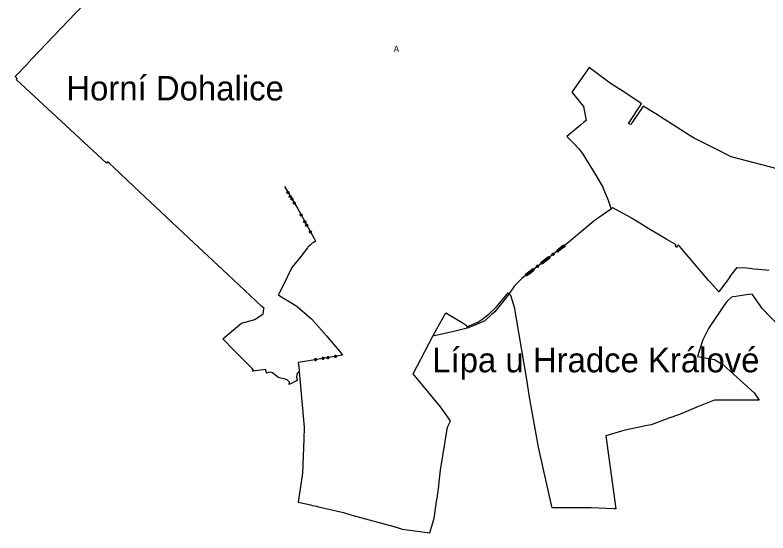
# Model space of a CAD drawing. Extents: x -648929 to -645777, y -1033280 to -1031329.
# Drawn here: x -648565 to -647340, y -1033165 to -1032322 of the extents above; entities that cross this region are included whole.
import ezdxf

# ---------------------------------------------------------------- set-up
doc = ezdxf.new("R2010")
doc.units = 0
for name, color, linetype in [('HRA_KU', 7, 'Continuous'), ('HRA_OK', 7, 'Continuous'), ('KU_RES', 7, 'Continuous'), ('OVNE_PRE', 7, 'Continuous'), ('OVNE_SET', 7, 'Continuous'), ('OVNI_SET', 7, 'Continuous'), ('POZN', 7, 'Continuous')]:
    doc.layers.add(name, color=color, linetype=linetype)

msp = doc.modelspace()

# ---------------------------------------------------------------- linework, layer by layer
at = {"layer": 'HRA_KU'}
for points in [[(-648126.7, -1032601), (-648105, -1032637.7), (-648078.9, -1032684.8), (-648076.1, -1032690.2), (-648078.2, -1032691.6), (-648081.4, -1032693.6), (-648084.7, -1032696.6), (-648088.4, -1032700), (-648089.1, -1032700.8), (-648100.1, -1032714.9), (-648114.4, -1032733), (-648121, -1032746.4), (-648122.3, -1032749), (-648136.4, -1032777.7), (-648130.7, -1032781.1), (-648116.1, -1032789.9), (-648106.3, -1032795.8), (-648085.2, -1032814.5), (-648082.8, -1032816.5), (-648058.4, -1032844.2), (-648034.5, -1032872.8), (-648032.2, -1032876), (-648087, -1032884.8), (-648104.3, -1032887.5), (-648103.6, -1032891.5), (-648103.4, -1032893.3), (-648102.6, -1032902.3)], [(-648119.2, -1032610.7), (-648119.5, -1032612), (-648120.7, -1032612.7), (-648122, -1032612.3), (-648122.6, -1032611.2), (-648122.3, -1032609.9), (-648121.2, -1032609.2), (-648119.9, -1032609.5), (-648119.2, -1032610.7), (-648119.4, -1032610.7), (-648120, -1032609.7), (-648120.5, -1032609.5), (-648119.5, -1032611.3), (-648119.6, -1032611.8), (-648121.1, -1032609.4), (-648121.4, -1032609.6), (-648120, -1032612), (-648120.3, -1032612.2), (-648121.8, -1032609.8), (-648122.1, -1032610), (-648120.7, -1032612.4), (-648121.2, -1032612.3), (-648122.2, -1032610.6), (-648122.4, -1032611.1), (-648121.8, -1032612.2)], [(-648115.3, -1032617.2), (-648115.6, -1032618.5), (-648116.8, -1032619.2), (-648118.1, -1032618.9), (-648118.7, -1032617.7), (-648118.4, -1032616.4), (-648117.3, -1032615.7), (-648116, -1032616.1), (-648115.3, -1032617.2), (-648115.5, -1032617.3), (-648116.1, -1032616.3), (-648116.6, -1032616.1), (-648115.6, -1032617.8), (-648115.7, -1032618.4), (-648117.2, -1032616), (-648117.5, -1032616.2), (-648116.1, -1032618.6), (-648116.4, -1032618.8), (-648117.9, -1032616.4), (-648118.2, -1032616.6), (-648116.8, -1032619), (-648117.3, -1032618.9), (-648118.3, -1032617.1), (-648118.5, -1032617.7), (-648117.9, -1032618.7)], [(-648112.8, -1032621.4), (-648113.1, -1032622.7), (-648114.3, -1032623.4), (-648115.6, -1032623.1), (-648116.3, -1032621.9), (-648115.9, -1032620.6), (-648114.8, -1032619.9), (-648113.5, -1032620.3), (-648112.8, -1032621.4), (-648113, -1032621.4), (-648113.6, -1032620.4), (-648114.2, -1032620.2), (-648113.2, -1032621.9), (-648113.3, -1032622.5), (-648114.7, -1032620.1), (-648115.1, -1032620.3), (-648113.7, -1032622.7), (-648114, -1032622.9), (-648115.4, -1032620.5), (-648115.8, -1032620.7), (-648114.3, -1032623.1), (-648114.9, -1032623), (-648115.9, -1032621.2), (-648116.1, -1032621.8), (-648115.4, -1032622.8)], [(-648108.9, -1032628), (-648109.2, -1032629.3), (-648110.4, -1032630), (-648111.7, -1032629.6), (-648112.4, -1032628.5), (-648112, -1032627.2), (-648110.9, -1032626.5), (-648109.6, -1032626.8), (-648108.9, -1032628), (-648109.1, -1032628), (-648109.7, -1032626.9), (-648110.3, -1032626.8), (-648109.3, -1032628.5), (-648109.4, -1032629.1), (-648110.8, -1032626.6), (-648111.2, -1032626.8), (-648109.8, -1032629.3), (-648110.1, -1032629.5), (-648111.5, -1032627.1), (-648111.9, -1032627.3), (-648110.4, -1032629.7), (-648111, -1032629.5), (-648112, -1032627.8), (-648112.2, -1032628.4), (-648111.5, -1032629.4)], [(-648097.7, -1032647.6), (-648098.1, -1032648.8), (-648099.2, -1032649.5), (-648100.5, -1032649.1), (-648101.2, -1032647.9), (-648100.8, -1032646.7), (-648099.6, -1032646), (-648098.3, -1032646.4), (-648097.7, -1032647.6), (-648097.9, -1032647.6), (-648098.5, -1032646.6), (-648099, -1032646.4), (-648098, -1032648.2), (-648098.2, -1032648.7), (-648099.6, -1032646.2), (-648099.9, -1032646.4), (-648098.6, -1032648.9), (-648098.9, -1032649.1), (-648100.3, -1032646.6), (-648100.6, -1032646.8), (-648099.3, -1032649.3), (-648099.8, -1032649.1), (-648100.8, -1032647.4), (-648100.9, -1032647.9), (-648100.3, -1032649)], [(-648091.6, -1032658.5), (-648092, -1032659.8), (-648093.2, -1032660.4), (-648094.5, -1032660.1), (-648095.1, -1032658.9), (-648094.8, -1032657.6), (-648093.6, -1032656.9), (-648092.3, -1032657.3), (-648091.6, -1032658.5), (-648091.9, -1032658.5), (-648092.5, -1032657.4), (-648093, -1032657.2), (-648092, -1032659), (-648092.2, -1032659.5), (-648093.6, -1032657.1), (-648093.9, -1032657.3), (-648092.5, -1032659.7), (-648092.9, -1032659.9), (-648094.3, -1032657.5), (-648094.6, -1032657.7), (-648093.2, -1032660.1), (-648093.8, -1032660), (-648094.8, -1032658.2), (-648094.9, -1032658.8), (-648094.3, -1032659.8)], [(-648088.6, -1032664), (-648089, -1032665.3), (-648090.1, -1032666), (-648091.4, -1032665.6), (-648092.1, -1032664.4), (-648091.7, -1032663.1), (-648090.5, -1032662.5), (-648089.2, -1032662.8), (-648088.6, -1032664), (-648088.8, -1032664.1), (-648089.4, -1032663), (-648089.9, -1032662.9), (-648088.9, -1032664.6), (-648089.1, -1032665.1), (-648090.4, -1032662.7), (-648090.8, -1032662.9), (-648089.4, -1032665.3), (-648089.8, -1032665.5), (-648091.1, -1032663.1), (-648091.5, -1032663.3), (-648090.1, -1032665.7), (-648090.7, -1032665.6), (-648091.7, -1032663.8), (-648091.8, -1032664.4), (-648091.2, -1032665.4)], [(-648082.5, -1032674.9), (-648082.9, -1032676.2), (-648084.1, -1032676.9), (-648085.4, -1032676.5), (-648086, -1032675.3), (-648085.7, -1032674), (-648084.5, -1032673.4), (-648083.2, -1032673.8), (-648082.5, -1032674.9), (-648082.8, -1032674.9), (-648083.4, -1032673.9), (-648083.9, -1032673.7), (-648082.9, -1032675.5), (-648083.1, -1032676), (-648084.4, -1032673.5), (-648084.8, -1032673.7), (-648083.4, -1032676.2), (-648083.8, -1032676.4), (-648085.1, -1032673.9), (-648085.5, -1032674.1), (-648084.1, -1032676.6), (-648084.7, -1032676.4), (-648085.6, -1032674.7), (-648085.8, -1032675.2), (-648085.2, -1032676.3)], [(-647885.1, -1032844.7), (-647878.8, -1032832.9), (-647863.9, -1032806.9), (-647837.3, -1032822.8), (-647831.1, -1032826.9), (-647830, -1032829.4), (-647812.1, -1032821.9), (-647805.7, -1032817.6), (-647793.9, -1032809), (-647781.9, -1032796.9), (-647762.6, -1032774.4), (-647760.8, -1032775.8)], [(-648076.5, -1032884.7), (-648077.6, -1032883.9), (-648077.8, -1032882.6), (-648077, -1032881.5), (-648075.7, -1032881.3), (-648074.6, -1032882.1), (-648074.4, -1032883.4), (-648075.2, -1032884.5), (-648076.5, -1032884.7), (-648076.4, -1032884.5), (-648075.2, -1032884.3), (-648074.9, -1032883.8), (-648076.8, -1032884.1), (-648077.3, -1032883.8), (-648074.5, -1032883.4), (-648074.6, -1032883), (-648077.4, -1032883.4), (-648077.4, -1032883), (-648074.7, -1032882.6), (-648074.7, -1032882.2), (-648077.5, -1032882.6), (-648077.2, -1032882.2), (-648075.2, -1032881.9), (-648075.6, -1032881.5), (-648076.8, -1032881.7)], [(-648064.2, -1032882.7), (-648065.2, -1032882), (-648065.5, -1032880.6), (-648064.7, -1032879.5), (-648063.3, -1032879.3), (-648062.2, -1032880.1), (-648062, -1032881.4), (-648062.8, -1032882.5), (-648064.2, -1032882.7), (-648064.1, -1032882.5), (-648062.9, -1032882.3), (-648062.6, -1032881.9), (-648064.6, -1032882.2), (-648065.1, -1032881.9), (-648062.3, -1032881.4), (-648062.3, -1032881), (-648065.1, -1032881.5), (-648065.2, -1032881.1), (-648062.4, -1032880.6), (-648062.5, -1032880.2), (-648065.2, -1032880.7), (-648064.9, -1032880.2), (-648062.9, -1032879.9), (-648063.4, -1032879.6), (-648064.6, -1032879.8)], [(-648056.3, -1032881.5), (-648057.4, -1032880.7), (-648057.6, -1032879.4), (-648056.8, -1032878.3), (-648055.5, -1032878.1), (-648054.4, -1032878.9), (-648054.2, -1032880.2), (-648055, -1032881.3), (-648056.3, -1032881.5), (-648056.2, -1032881.3), (-648055, -1032881.1), (-648054.7, -1032880.6), (-648056.7, -1032880.9), (-648057.1, -1032880.6), (-648054.3, -1032880.2), (-648054.4, -1032879.8), (-648057.2, -1032880.2), (-648057.2, -1032879.8), (-648054.5, -1032879.4), (-648054.5, -1032879), (-648057.3, -1032879.4), (-648057, -1032879), (-648055, -1032878.6), (-648055.5, -1032878.3), (-648056.6, -1032878.5)], [(-648044, -1032879.5), (-648045.1, -1032878.7), (-648045.3, -1032877.4), (-648044.5, -1032876.3), (-648043.1, -1032876.1), (-648042.1, -1032876.9), (-648041.8, -1032878.2), (-648042.6, -1032879.3), (-648044, -1032879.5), (-648043.9, -1032879.3), (-648042.8, -1032879.1), (-648042.4, -1032878.7), (-648044.4, -1032879), (-648044.9, -1032878.7), (-648042.1, -1032878.2), (-648042.2, -1032877.8), (-648044.9, -1032878.3), (-648045, -1032877.9), (-648042.2, -1032877.4), (-648042.3, -1032877), (-648045.1, -1032877.5), (-648044.7, -1032877), (-648042.7, -1032876.7), (-648043.2, -1032876.4), (-648044.4, -1032876.6)]]:
    msp.add_lwpolyline(points, dxfattribs=at)
at = {"layer": 'HRA_OK'}
msp.add_line((-647761.2, -1032775.5), (-647760.8, -1032775.8), dxfattribs=at)
for points in [[(-647595.3, -1032637.9), (-647599.4, -1032641), (-647614.3, -1032651.2), (-647620.5, -1032655.4), (-647626.8, -1032660.5), (-647660.2, -1032688.8), (-647664, -1032691.8), (-647740.7, -1032751.1), (-647752.6, -1032763.1), (-647758.2, -1032771.5), (-647761.2, -1032775.5)], [(-647670.2, -1032698.8), (-647675.2, -1032702.7), (-647680.3, -1032706.6), (-647682.1, -1032708), (-647684.2, -1032705.2), (-647679.2, -1032701.3), (-647674.2, -1032697.4), (-647672.3, -1032696), (-647670.2, -1032698.8), (-647670.6, -1032698.7), (-647675.6, -1032702.6), (-647680.7, -1032706.4), (-647682, -1032707.5), (-647682.3, -1032707.2), (-647677.2, -1032703.3), (-647672.2, -1032699.4), (-647670.9, -1032698.4), (-647671.1, -1032698), (-647676.1, -1032701.9), (-647681.2, -1032705.8), (-647682.5, -1032706.8), (-647682.8, -1032706.5), (-647677.7, -1032702.6), (-647672.7, -1032698.8), (-647671.4, -1032697.7), (-647671.6, -1032697.4), (-647676.6, -1032701.3), (-647681.6, -1032705.2), (-647683, -1032706.2), (-647683.2, -1032705.9), (-647678.2, -1032702), (-647673.2, -1032698.1), (-647671.8, -1032697.1), (-647672.1, -1032696.8), (-647677.1, -1032700.7), (-647682.1, -1032704.5), (-647683.5, -1032705.6), (-647683.7, -1032705.3), (-647678.7, -1032701.4), (-647673.7, -1032697.5), (-647672.3, -1032696.5)], [(-647695.5, -1032718.4), (-647700.6, -1032722.3), (-647705.6, -1032726.1), (-647707.4, -1032727.5), (-647709.6, -1032724.8), (-647704.5, -1032720.9), (-647699.5, -1032717), (-647697.7, -1032715.6), (-647695.5, -1032718.4), (-647696, -1032718.2), (-647701, -1032722.1), (-647706, -1032726), (-647707.4, -1032727), (-647707.6, -1032726.7), (-647702.6, -1032722.8), (-647697.5, -1032719), (-647696.2, -1032717.9), (-647696.4, -1032717.6), (-647701.5, -1032721.5), (-647706.5, -1032725.4), (-647707.8, -1032726.4), (-647708.1, -1032726.1), (-647703.1, -1032722.2), (-647698, -1032718.3), (-647696.7, -1032717.3), (-647696.9, -1032717), (-647702, -1032720.9), (-647707, -1032724.7), (-647708.3, -1032725.8), (-647708.6, -1032725.5), (-647703.6, -1032721.6), (-647698.5, -1032717.7), (-647697.2, -1032716.7), (-647697.4, -1032716.3), (-647702.5, -1032720.2), (-647707.5, -1032724.1), (-647708.8, -1032725.1), (-647709.1, -1032724.8), (-647704, -1032720.9), (-647699, -1032717.1), (-647697.7, -1032716)], [(-647695.1, -1032718), (-647700.2, -1032721.9), (-647705.2, -1032725.8), (-647707, -1032727.2), (-647709.2, -1032724.4), (-647704.1, -1032720.6), (-647699.1, -1032716.7), (-647697.3, -1032715.3), (-647695.1, -1032718), (-647695.6, -1032718), (-647700.7, -1032721.9), (-647705.7, -1032725.7), (-647707, -1032726.8), (-647707.3, -1032726.5), (-647702.2, -1032722.6), (-647697.2, -1032718.7), (-647695.9, -1032717.7), (-647696.1, -1032717.3), (-647701.1, -1032721.2), (-647706.2, -1032725.1), (-647707.5, -1032726.1), (-647707.8, -1032725.8), (-647702.7, -1032722), (-647697.7, -1032718.1), (-647696.4, -1032717), (-647696.6, -1032716.7), (-647701.6, -1032720.6), (-647706.7, -1032724.5), (-647708, -1032725.5), (-647708.3, -1032725.2), (-647703.2, -1032721.3), (-647698.2, -1032717.4), (-647696.9, -1032716.4), (-647697.1, -1032716.1), (-647702.1, -1032720), (-647707.2, -1032723.8), (-647708.5, -1032724.9), (-647708.7, -1032724.6), (-647703.7, -1032720.7), (-647698.7, -1032716.8), (-647697.3, -1032715.8)], [(-647688.2, -1032712.5), (-647689.3, -1032713.3), (-647690.6, -1032713.1), (-647691.4, -1032712.1), (-647691.2, -1032710.7), (-647690.2, -1032709.9), (-647688.8, -1032710.1), (-647688, -1032711.2), (-647688.2, -1032712.5), (-647688.3, -1032712.4), (-647689.3, -1032713.1), (-647689.9, -1032713), (-647688.3, -1032711.8), (-647688.2, -1032711.2), (-647690.4, -1032712.9), (-647690.7, -1032712.6), (-647688.4, -1032710.9), (-647688.7, -1032710.6), (-647690.9, -1032712.3), (-647691.2, -1032712), (-647688.9, -1032710.3), (-647689.5, -1032710.2), (-647691.1, -1032711.4), (-647691, -1032710.9), (-647690.1, -1032710.1)], [(-647720.5, -1032737.6), (-647725.5, -1032741.5), (-647730.5, -1032745.4), (-647732.4, -1032746.8), (-647734.5, -1032744), (-647729.5, -1032740.1), (-647724.4, -1032736.3), (-647722.6, -1032734.8), (-647720.5, -1032737.6), (-647721, -1032737.6), (-647726, -1032741.4), (-647731, -1032745.3), (-647732.4, -1032746.4), (-647732.6, -1032746), (-647727.6, -1032742.2), (-647722.6, -1032738.3), (-647721.2, -1032737.2), (-647721.5, -1032736.9), (-647726.5, -1032740.8), (-647731.5, -1032744.7), (-647732.9, -1032745.7), (-647733.1, -1032745.4), (-647728.1, -1032741.5), (-647723.1, -1032737.6), (-647721.7, -1032736.6), (-647721.9, -1032736.3), (-647727, -1032740.2), (-647732, -1032744), (-647733.3, -1032745.1), (-647733.6, -1032744.8), (-647728.6, -1032740.9), (-647723.5, -1032737), (-647722.2, -1032736), (-647722.4, -1032735.7), (-647727.5, -1032739.5), (-647732.5, -1032743.4), (-647733.8, -1032744.5), (-647734.1, -1032744.1), (-647729.1, -1032740.3), (-647724, -1032736.4), (-647722.7, -1032735.3)], [(-647713.5, -1032732.1), (-647714.6, -1032732.9), (-647715.9, -1032732.7), (-647716.8, -1032731.6), (-647716.6, -1032730.3), (-647715.5, -1032729.5), (-647714.2, -1032729.7), (-647713.4, -1032730.7), (-647713.5, -1032732.1), (-647713.7, -1032731.9), (-647714.6, -1032732.7), (-647715.2, -1032732.6), (-647713.6, -1032731.4), (-647713.5, -1032730.8), (-647715.8, -1032732.5), (-647716, -1032732.2), (-647713.8, -1032730.5), (-647714, -1032730.2), (-647716.3, -1032731.9), (-647716.5, -1032731.6), (-647714.3, -1032729.9), (-647714.8, -1032729.8), (-647716.4, -1032731), (-647716.4, -1032730.5), (-647715.4, -1032729.7)]]:
    msp.add_lwpolyline(points, dxfattribs=at)
at = {"layer": 'OVNE_PRE'}
msp.add_lwpolyline([(-648394.3, -1032243.5), (-648465.8, -1032318.5), (-648537.4, -1032393.4), (-648546.3, -1032402.8)], dxfattribs=at)
at = {"layer": 'OVNE_SET'}
for points in [[(-648179.8, -1032897.1), (-648208.6, -1032868.1), (-648227, -1032849.4), (-648215.9, -1032839.7), (-648196.7, -1032823.5), (-648175, -1032817.7), (-648161, -1032808.4), (-648159.9, -1032800.3), (-648159.8, -1032799.9), (-648163.2, -1032796.6), (-648218.9, -1032744.2), (-648273.8, -1032693.1), (-648371.6, -1032601), (-648404.7, -1032569.9), (-648410.5, -1032564.5), (-648414.4, -1032560.8), (-648416.2, -1032563), (-648562.9, -1032427), (-648561.2, -1032425.1), (-648564.8, -1032422.1), (-648546.3, -1032402.8)], [(-647758.5, -1032778.5), (-647760.8, -1032775.8), (-647784.5, -1032805.3), (-647789, -1032808.8), (-647800.8, -1032820), (-647817.7, -1032827.5), (-647829.5, -1032831.8), (-647848.9, -1032836.7), (-647885.1, -1032844.7)], [(-647309.6, -1032841.7), (-647348.7, -1032800.6), (-647365.8, -1032776.4), (-647371.8, -1032777), (-647399.6, -1032781.3)], [(-647399.6, -1032781.3), (-647406.2, -1032787.6), (-647408.2, -1032790), (-647410.4, -1032792.6), (-647436.8, -1032832.5), (-647445.9, -1032850.6), (-647454.6, -1032878.1), (-647426.8, -1032883.1), (-647413.1, -1032891.6), (-647362.3, -1032937.3), (-647354.3, -1032948.9), (-647404.7, -1032949.1), (-647421.5, -1032949.2), (-647427.2, -1032949.1), (-647431.1, -1032950.7), (-647455.6, -1032960.7), (-647483.7, -1032972.2), (-647501.2, -1032978.6), (-647530.2, -1032989.2), (-647539.3, -1032991.1), (-647569.8, -1032997.6), (-647578.4, -1032999.4), (-647603.8, -1033006.9), (-647587.7, -1033125.8), (-647588.1, -1033125.9), (-647590.9, -1033125.8), (-647627.9, -1033124.5), (-647691.3, -1033124.6), (-647698.2, -1033093.2), (-647713.1, -1033025.4), (-647728.2, -1032944.4), (-647732.5, -1032915.2), (-647748.9, -1032816.5), (-647751.9, -1032800), (-647758.5, -1032778.5)], [(-648102.6, -1032902.3), (-648094.3, -1032993), (-648095.1, -1033012.3), (-648097.3, -1033068.1), (-648104.2, -1033115.3), (-648091.1, -1033118.1), (-648084.3, -1033119.6), (-648082.4, -1033120), (-648081, -1033120.3), (-648074.7, -1033121.7), (-648071.4, -1033122.5), (-648030.6, -1033132.2), (-648027.1, -1033133.2), (-648014.6, -1033136.7), (-647948.5, -1033154.9), (-647945.2, -1033155.8), (-647944.9, -1033155.9), (-647934.9, -1033159), (-647889.9, -1033165.3), (-647888.2, -1033159.9), (-647883, -1033141.1), (-647879, -1033114.2), (-647877.7, -1033105.7), (-647877.5, -1033104.4), (-647876.3, -1033096.5), (-647875.9, -1033093.3), (-647874.3, -1033077.5), (-647872.8, -1033063.2), (-647861.2, -1032992.9), (-647857.7, -1032985.4), (-647856.2, -1032983.3), (-647859.4, -1032979.1), (-647872.7, -1032960.1), (-647917.3, -1032906.3), (-647885.1, -1032844.7)], [(-648102.6, -1032902.3), (-648105.9, -1032905.9), (-648106.8, -1032911.4), (-648105.7, -1032916.8), (-648118.9, -1032923.8), (-648118.6, -1032919.5), (-648121.9, -1032915.7), (-648127, -1032914.1), (-648132.5, -1032913.4), (-648137.5, -1032911.4), (-648146.2, -1032904.4), (-648149.4, -1032903.6), (-648152.5, -1032904), (-648155.8, -1032905.2), (-648156, -1032903.9), (-648156.5, -1032903), (-648156.6, -1032899.2), (-648178.6, -1032901.9), (-648176.1, -1032900.8), (-648179.8, -1032897.1)]]:
    msp.add_lwpolyline(points, dxfattribs=at)
at = {"layer": 'OVNI_SET'}
for points in [[(-647310.2, -1032576.3), (-647399.9, -1032552.9), (-647425.2, -1032539.7), (-647460.3, -1032522.2), (-647468.2, -1032517.6), (-647522.6, -1032483.1), (-647543, -1032470.1), (-647561.2, -1032496.7), (-647563.4, -1032500), (-647567.1, -1032498.5), (-647545.7, -1032466.3), (-647547.8, -1032465), (-647581.2, -1032442.9), (-647581.7, -1032442.6), (-647596.8, -1032432.8), (-647606.9, -1032425.2), (-647630.8, -1032407.2), (-647659.3, -1032447.5), (-647640.3, -1032471.1), (-647635.8, -1032493.9), (-647639.9, -1032497.2), (-647645, -1032501.3), (-647667.4, -1032519.6), (-647656.6, -1032530.7), (-647647.6, -1032539.6), (-647641.8, -1032547.3), (-647635.3, -1032558.2), (-647634.3, -1032559.9), (-647621.4, -1032581.2), (-647609.4, -1032601.2), (-647605.9, -1032609.4), (-647600.9, -1032620.8), (-647599.2, -1032624.8), (-647595.3, -1032637.9)], [(-647402.2, -1032748.5), (-647404.4, -1032751.5), (-647420.2, -1032772.5), (-647433.2, -1032757.9), (-647436.4, -1032754.7), (-647438.3, -1032752.1), (-647441.8, -1032748.2), (-647484.2, -1032698.4), (-647486, -1032696.2), (-647488.2, -1032700.3), (-647491.1, -1032698.3), (-647489.6, -1032696.3), (-647504.3, -1032687.6), (-647519.2, -1032678.8), (-647533.7, -1032670.3), (-647548.7, -1032661.1), (-647562.3, -1032652.8), (-647563.9, -1032651.9), (-647592.2, -1032635.9), (-647595.3, -1032637.9)], [(-647402.2, -1032748.5), (-647390.2, -1032732.8), (-647374.8, -1032733.8), (-647370.2, -1032734.4), (-647363.3, -1032735), (-647355, -1032735.7), (-647338, -1032737.5)]]:
    msp.add_lwpolyline(points, dxfattribs=at)

# ---------------------------------------------------------------- texts
at = {"layer": 'KU_RES'}
for s, p in [('Horní Dohalice', (-648481.4, -1032461)), ('Lípa u Hradce Králové', (-647886.1, -1032903.7))]:
    msp.add_text(s, height=40, dxfattribs=at).set_placement(p)
at = {"layer": 'POZN'}
msp.add_text('A', height=10, dxfattribs=at).set_placement((-647949, -1032382.1))

doc.saveas('drawing.dxf')
